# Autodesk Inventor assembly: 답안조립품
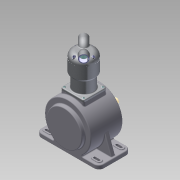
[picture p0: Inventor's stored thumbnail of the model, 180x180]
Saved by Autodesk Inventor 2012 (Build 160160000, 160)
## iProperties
Created: 2015-06
Part Number: 답안조립품
Document SubType Name: Assembly
Designer: Administrator
Author: Administrator
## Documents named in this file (12)
- C:\Documents and Settings\Administrator\바탕 화면\450605v1005\답안조립품.iam
- C:\Documents and Settings\Administrator\바탕 화면\450605v1005\본체.ipt
- C:\Documents and Settings\Administrator\바탕 화면\450605v1005\베어링 6204.ipt
- C:\Documents and Settings\Administrator\바탕 화면\450605v1005\크랭크 서브축.ipt
- C:\Documents and Settings\Administrator\바탕 화면\450605v1005\메인 크랭크 축-구동부.ipt
- C:\Documents and Settings\Administrator\바탕 화면\450605v1005\커넥팅 로드.ipt
- C:\Documents and Settings\Administrator\바탕 화면\450605v1005\실린더.ipt
- C:\Documents and Settings\Administrator\바탕 화면\450605v1005\실린더헤드.ipt
- C:\Documents and Settings\Administrator\바탕 화면\450605v1005\메인커버.ipt
- C:\Documents and Settings\Administrator\바탕 화면\450605v1005\오일실.ipt
- C:\Documents and Settings\Administrator\바탕 화면\450605v1005\M4x0.7.ipt
- C:\Documents and Settings\Administrator\바탕 화면\450605v1005\M5x0.8.ipt
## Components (8 placed, 2 different names)
1. M5x0.8:2
2. M5x0.8:3
3. M5x0.8:4
4. M5x0.8:5
5. M4x0.7:1
6. M4x0.7:2
7. M4x0.7:3
8. M4x0.7:4
